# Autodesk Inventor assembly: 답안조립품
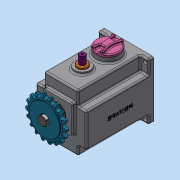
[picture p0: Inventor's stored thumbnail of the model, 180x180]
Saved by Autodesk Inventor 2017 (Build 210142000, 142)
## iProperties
Part Number: 답안조립품
Material: 일반
Document SubType Name: Assembly
Designer: MRC
Author: MRC
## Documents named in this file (16)
- C:\Users\MRC\Desktop\720212V1007\답안조립품.iam
- C:\Users\MRC\Desktop\720212V1007\본체.ipt
- C:\Users\MRC\Desktop\720212V1007\멈춤나사 M3.ipt
- C:\Users\MRC\Desktop\720212V1007\메인 축.ipt
- C:\Users\MRC\Desktop\720212V1007\베어링 608.ipt
- C:\Users\MRC\Desktop\720212V1007\베어링 6003.ipt
- C:\Users\MRC\Desktop\720212V1007\볼트 M4 x 10.ipt
- C:\Users\MRC\Desktop\720212V1007\부시.ipt
- C:\Users\MRC\Desktop\720212V1007\상부 캡.ipt
- C:\Users\MRC\Desktop\720212V1007\서브 축.ipt
- C:\Users\MRC\Desktop\720212V1007\스프로킷.ipt
- C:\Users\MRC\Desktop\720212V1007\슬라이더.ipt
- C:\Users\MRC\Desktop\720212V1007\오일 실 8 x 22 x 7.ipt
- C:\Users\MRC\Desktop\720212V1007\오일 실 17 x 32 x 8.ipt
- C:\Users\MRC\Desktop\720212V1007\커버.ipt
- C:\Users\MRC\Desktop\720212V1007\키 5 x 5.ipt
